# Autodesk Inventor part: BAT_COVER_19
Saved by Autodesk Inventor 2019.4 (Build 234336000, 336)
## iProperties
Created: 2020-05
Part Number: BAT_COVER_19
Material: Generic
Document SubType Name: Modeling
Designer: Administrator
Density: 1 g/cm^3
Appearance: Default
Title: BAT_COVER_19
Author: Administrator
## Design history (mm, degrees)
feature "Body1"
body "Solid1"
